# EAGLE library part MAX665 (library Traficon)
Switched-capcitor VOLTAGE CONVERTER
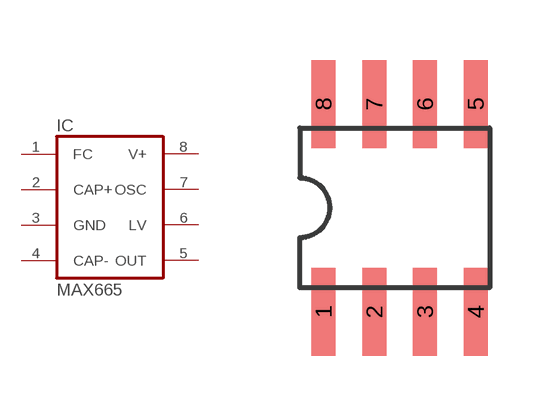
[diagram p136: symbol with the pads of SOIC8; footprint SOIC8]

Designator prefix IC

## MAX665  [SOIC8]
1  FC  pas
2  CAP+
3  GND  pwr
4  CAP-
5  OUT  out
6  LV  pas
7  OSC  out
8  V+  pwr

## Footprint SOIC8 (pad centres in mm)
Small Outline IC
smd 0.6 x 2.2: 1 -1.905,-2.6; 2 -0.635,-2.6; 3 0.635,-2.6; 4 1.905,-2.6; 5 1.905,2.6; 6 0.635,2.6; 7 -0.635,2.6; 8 -1.905,2.6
